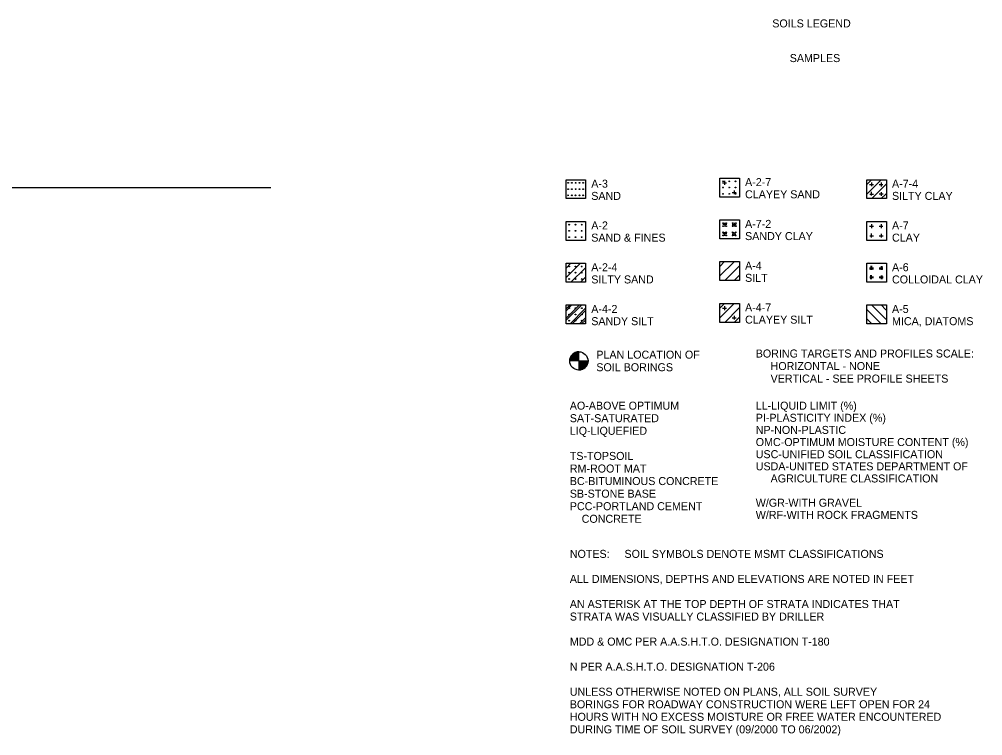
# Model space of a CAD drawing. Extents: x 1.3 to 42.5, y -2.5 to 22.6.
# Drawn here: x 28.02 to 42.47, y 11.81 to 22.56 of the extents above; entities that cross this region are included whole.
import ezdxf

# ---------------------------------------------------------------- set-up
doc = ezdxf.new("R2010")
doc.units = 0
doc.layers.add('B-SOIL-TEXT', color=7, linetype='Continuous')

msp = doc.modelspace()

# ---------------------------------------------------------------- linework, layer by layer
at = {"layer": 'B-SOIL-TEXT'}
for p, q in [((38.568, 20.107), (38.627, 20.107)), ((40.802, 20.154), (40.732, 20.082)), ((40.945, 20.153), (40.732, 19.939)), ((40.945, 20.11), (40.945, 20.053)), ((41.024, 20.089), (41.017, 20.082)), ((20.128, 20.038), (31.791, 20.038)), ((38.713, 19.964), (38.771, 19.964)), ((40.773, 20.082), (40.831, 20.082)), ((40.803, 19.915), (40.803, 19.971)), ((41.016, 20.082), (40.804, 19.87)), ((40.915, 20.082), (40.973, 20.082)), ((41.024, 19.947), (41.017, 19.939)), ((40.775, 19.939), (40.833, 19.939)), ((40.917, 19.94), (40.976, 19.94)), ((41.016, 19.939), (40.947, 19.87)), ((38.631, 19.48), (38.573, 19.48)), ((38.6, 19.508), (38.6, 19.451)), ((38.6, 19.312), (38.6, 19.369)), ((38.71, 19.48), (38.769, 19.48)), ((38.74, 19.312), (38.74, 19.369)), ((38.741, 19.508), (38.741, 19.451)), ((40.773, 19.457), (40.831, 19.457)), ((40.915, 19.456), (40.973, 19.456)), ((40.945, 19.485), (40.945, 19.428)), ((38.631, 19.34), (38.573, 19.34)), ((38.709, 19.34), (38.768, 19.34)), ((40.775, 19.314), (40.833, 19.314)), ((40.803, 19.289), (40.803, 19.346)), ((40.917, 19.314), (40.976, 19.314)), ((36.291, 18.901), (36.22, 18.829)), ((36.434, 18.9), (36.22, 18.687)), ((36.505, 18.829), (36.293, 18.617)), ((36.513, 18.836), (36.505, 18.829)), ((38.598, 18.925), (38.527, 18.853)), ((38.741, 18.924), (38.527, 18.71)), ((38.812, 18.853), (38.6, 18.64)), ((38.82, 18.86), (38.812, 18.853)), ((40.773, 18.83), (40.831, 18.83)), ((40.773, 18.819), (40.831, 18.819)), ((40.915, 18.83), (40.973, 18.83)), ((40.915, 18.819), (40.973, 18.819)), ((40.945, 18.858), (40.945, 18.801)), ((40.957, 18.858), (40.957, 18.801)), ((36.505, 18.687), (36.435, 18.617)), ((36.513, 18.694), (36.505, 18.687)), ((38.812, 18.71), (38.742, 18.64)), ((38.82, 18.717), (38.812, 18.71)), ((40.775, 18.699), (40.833, 18.699)), ((40.775, 18.688), (40.833, 18.688)), ((40.791, 18.663), (40.791, 18.72)), ((40.803, 18.663), (40.803, 18.72)), ((40.917, 18.699), (40.976, 18.699)), ((40.917, 18.688), (40.976, 18.688)), ((36.419, 18.275), (36.22, 18.076)), ((36.274, 18.274), (36.221, 18.219)), ((36.307, 18.275), (36.222, 18.188)), ((36.45, 18.274), (36.222, 18.046)), ((36.507, 18.221), (36.279, 17.992)), ((36.513, 18.224), (36.508, 18.219)), ((38.598, 18.298), (38.527, 18.226)), ((38.741, 18.297), (38.527, 18.084)), ((38.568, 18.226), (38.627, 18.226)), ((38.812, 18.226), (38.6, 18.014)), ((38.82, 18.233), (38.812, 18.226)), ((40.805, 18.274), (41.018, 18.06)), ((40.948, 18.275), (41.018, 18.202)), ((36.506, 18.187), (36.311, 17.992)), ((36.506, 18.077), (36.421, 17.992)), ((36.513, 18.081), (36.508, 18.076)), ((36.513, 18.191), (36.51, 18.188)), ((38.713, 18.084), (38.771, 18.084)), ((38.812, 18.084), (38.742, 18.014)), ((38.82, 18.091), (38.812, 18.084)), ((40.734, 18.202), (40.946, 17.99)), ((41.021, 18.202), (41.024, 18.199)), ((36.505, 18.044), (36.452, 17.991)), ((36.513, 18.049), (36.509, 18.046)), ((40.734, 18.06), (40.804, 17.99)), ((41.021, 18.06), (41.024, 18.057)), ((36.413, 17.436), (36.413, 17.573)), ((36.413, 17.436), (36.276, 17.436)), ((36.413, 17.436), (36.413, 17.436)), ((36.413, 17.436), (36.413, 17.3)), ((36.413, 17.436), (36.549, 17.436))]:
    msp.add_line(p, q, dxfattribs=at)
for points in [[(36.22, 20.154), (36.513, 20.154), (36.513, 19.87), (36.22, 19.87)], [(38.527, 20.178), (38.82, 20.178), (38.82, 19.893), (38.527, 19.893)], [(40.732, 20.154), (41.024, 20.154), (41.024, 19.87), (40.732, 19.87)], [(36.22, 19.528), (36.513, 19.528), (36.513, 19.243), (36.22, 19.243)], [(38.527, 19.551), (38.82, 19.551), (38.82, 19.267), (38.527, 19.267)], [(40.732, 19.528), (41.024, 19.528), (41.024, 19.243), (40.732, 19.243)], [(36.22, 18.901), (36.513, 18.901), (36.513, 18.617), (36.22, 18.617)], [(38.527, 18.925), (38.82, 18.925), (38.82, 18.64), (38.527, 18.64)], [(40.732, 18.901), (41.024, 18.901), (41.024, 18.617), (40.732, 18.617)], [(36.22, 18.275), (36.513, 18.275), (36.513, 17.99), (36.22, 17.99)], [(38.527, 18.298), (38.82, 18.298), (38.82, 18.014), (38.527, 18.014)], [(40.732, 18.275), (41.024, 18.275), (41.024, 17.99), (40.732, 17.99)]]:
    msp.add_lwpolyline(points, close=True, dxfattribs=at)
for points in [[(38.598, 20.136), (38.598, 20.114), (38.598, 20.079)], [(40.802, 20.112), (40.802, 20.089), (40.802, 20.055)], [(38.741, 19.994), (38.741, 19.971), (38.741, 19.937)], [(40.945, 19.969), (40.945, 19.946), (40.945, 19.912)], [(40.802, 19.486), (40.802, 19.463), (40.802, 19.429)], [(40.945, 19.343), (40.945, 19.321), (40.945, 19.287)], [(40.791, 18.86), (40.791, 18.837), (40.791, 18.803)], [(40.802, 18.86), (40.802, 18.837), (40.802, 18.803)], [(40.945, 18.717), (40.945, 18.694), (40.945, 18.66)], [(40.957, 18.717), (40.957, 18.694), (40.957, 18.66)], [(38.598, 18.256), (38.598, 18.233), (38.598, 18.199)], [(38.741, 18.113), (38.741, 18.09), (38.741, 18.056)]]:
    msp.add_lwpolyline(points, dxfattribs=at)
for centre, radius in [((36.25, 20.106), 0.0057), ((36.307, 20.106), 0.0057), ((36.364, 20.106), 0.0057), ((36.421, 20.106), 0.0057), ((36.478, 20.106), 0.0057), ((38.574, 20.13), 0.0057), ((38.668, 20.13), 0.0057), ((38.761, 20.13), 0.0057), ((36.25, 20.013), 0.0057), ((36.307, 20.013), 0.0057), ((36.364, 20.013), 0.0057), ((36.421, 20.013), 0.0057), ((36.478, 20.013), 0.0057), ((38.574, 20.036), 0.0057), ((38.574, 19.943), 0.0057), ((38.668, 20.036), 0.0057), ((38.668, 19.943), 0.0057), ((38.761, 20.036), 0.0057), ((38.761, 19.943), 0.0057), ((36.249, 19.919), 0.0057), ((36.306, 19.919), 0.0057), ((36.363, 19.919), 0.0057), ((36.42, 19.919), 0.0057), ((36.477, 19.919), 0.0057), ((36.267, 19.48), 0.0057), ((36.267, 19.386), 0.0057), ((36.361, 19.48), 0.0057), ((36.361, 19.386), 0.0057), ((36.454, 19.48), 0.0057), ((36.454, 19.386), 0.0057), ((38.576, 19.502), 0.0057), ((38.576, 19.456), 0.0057), ((38.576, 19.364), 0.0057), ((38.622, 19.502), 0.0057), ((38.622, 19.456), 0.0057), ((38.622, 19.364), 0.0057), ((38.718, 19.364), 0.0057), ((38.719, 19.502), 0.0057), ((38.719, 19.456), 0.0057), ((38.764, 19.364), 0.0057), ((38.765, 19.502), 0.0057), ((38.765, 19.456), 0.0057), ((36.267, 19.293), 0.0057), ((36.361, 19.293), 0.0057), ((36.454, 19.293), 0.0057), ((38.576, 19.318), 0.0057), ((38.622, 19.318), 0.0057), ((38.718, 19.318), 0.0057), ((38.764, 19.318), 0.0057), ((36.267, 18.852), 0.0057), ((36.361, 18.852), 0.0057), ((36.454, 18.852), 0.0057), ((36.267, 18.759), 0.0057), ((36.267, 18.665), 0.0057), ((36.361, 18.759), 0.0057), ((36.361, 18.665), 0.0057), ((36.454, 18.759), 0.0057), ((36.454, 18.665), 0.0057), ((36.268, 18.227), 0.0057), ((36.362, 18.227), 0.0057), ((36.455, 18.227), 0.0057), ((36.268, 18.133), 0.0057), ((36.362, 18.133), 0.0057), ((36.455, 18.133), 0.0057), ((36.268, 18.04), 0.0057), ((36.362, 18.04), 0.0057), ((36.455, 18.04), 0.0057), ((36.412, 17.436), 0.137)]:
    msp.add_circle(centre, radius, dxfattribs=at)
for radius, start, end in [(0.137, 90.0009, 180.0009), (0.134, 90.0009, 180.0009), (0.131, 90.0009, 180.0009), (0.128, 90.0009, 180.0009), (0.125, 90.0009, 180.0009), (0.122, 90.0009, 180.0009), (0.12, 90.0009, 180.0009), (0.117, 90.0009, 180.0009), (0.114, 90.0009, 180.0009), (0.111, 90.0009, 180.0009), (0.108, 90.0009, 180.0009), (0.105, 90.0009, 180.0009), (0.103, 90.0009, 180.0009), (0.0997, 90.0009, 180.0009), (0.0968, 90.0009, 180.0009), (0.094, 90.0009, 180.0009), (0.0911, 90.0009, 180.0009), (0.0883, 90.0009, 180.0009), (0.0854, 90.0009, 180.0009), (0.0826, 90.0009, 180.0009), (0.0797, 90.0009, 180.0009), (0.0769, 90.0009, 180.0009), (0.074, 90.0009, 180.0009), (0.0712, 90.0009, 180.0009), (0.0683, 90.0009, 180.0009), (0.0655, 90.0009, 180.0009), (0.0626, 90.0009, 180.0009), (0.0598, 90.0009, 180.0009), (0.057, 90.0009, 180.0009), (0.0541, 90.0009, 180.0009), (0.0513, 90.0009, 180.0009), (0.0484, 90.0009, 180.0009), (0.0456, 90.0009, 180.0009), (0.0427, 90.0009, 180.0009), (0.0399, 90.0009, 180.0009), (0.037, 90.0009, 180.0009), (0.0342, 90.0009, 180.0009), (0.0313, 90.0009, 180.0009), (0.0285, 90.0009, 180.0009), (0.0256, 90.0009, 180.0009), (0.0228, 90.0009, 180.0009), (0.0199, 90.0009, 180.0009), (0.0171, 90.0009, 180.0009), (0.0142, 90.0009, 180.0009), (0.0114, 90.0009, 180.0009), (0.00854, 90.0009, 180.0009), (0.0057, 90.0009, 180.0009), (0.00285, 90.0009, 180.0009), (0.137, 270.0009, 0.0009), (0.134, 270.0009, 0.0009), (0.131, 270.0009, 0.0009), (0.128, 270.0009, 0.0009), (0.125, 270.0009, 0.0009), (0.122, 270.0009, 0.0009), (0.12, 270.0009, 0.0009), (0.117, 270.0009, 0.0009), (0.114, 270.0009, 0.0009), (0.111, 270.0009, 0.0009), (0.108, 270.0009, 0.0009), (0.105, 270.0009, 0.0009), (0.103, 270.0009, 0.0009), (0.0997, 270.0009, 0.0009), (0.0968, 270.0009, 0.0009), (0.094, 270.0009, 0.0009), (0.0911, 270.0009, 0.0009), (0.0883, 270.0009, 0.0009), (0.0854, 270.0009, 0.0009), (0.0826, 270.0009, 0.0009), (0.0797, 270.0009, 0.0009), (0.0769, 270.0009, 0.0009), (0.074, 270.0009, 0.0009), (0.0712, 270.0009, 0.0009), (0.0683, 270.0009, 0.0009), (0.0655, 270.0009, 0.0009), (0.0626, 270.0009, 0.0009), (0.0598, 270.0009, 0.0009), (0.057, 270.0009, 0.0009), (0.0541, 270.0009, 0.0009), (0.0513, 270.0009, 0.0009), (0.0484, 270.0009, 0.0009), (0.0456, 270.0009, 0.0009), (0.0427, 270.0009, 0.0009), (0.0399, 270.0009, 0.0009), (0.037, 270.0009, 0.0009), (0.0342, 270.0009, 0.0009), (0.0313, 270.0009, 0.0009), (0.0285, 270.0009, 0.0009), (0.0256, 270.0009, 0.0009), (0.0228, 270.0009, 0.0009), (0.0199, 270.0009, 0.0009), (0.0171, 270.0009, 0.0009), (0.0142, 270.0009, 0.0009), (0.0114, 270.0009, 0.0009), (0.00854, 270.0009, 0.0009), (0.0057, 270.0009, 0.0009), (0.00285, 270.0009, 0.0009)]:
    msp.add_arc((36.412, 17.436), radius, start, end, dxfattribs=at)

# ---------------------------------------------------------------- texts
for s, p in [('SOILS LEGEND', (39.313, 22.438)), ('SAMPLES', (39.575, 21.918)), ('A-3', (36.598, 20.034)), ('A-2-7', (38.905, 20.058)), ('A-7-4', (41.109, 20.034)), ('SAND', (36.598, 19.851)), ('CLAYEY SAND', (38.905, 19.875)), ('SILTY CLAY', (41.109, 19.851)), ('A-2', (36.598, 19.408)), ('A-7-2', (38.905, 19.431)), ('A-7', (41.109, 19.408)), ('SANDY CLAY', (38.905, 19.248)), ('SAND & FINES', (36.598, 19.225)), ('CLAY', (41.109, 19.225)), ('A-2-4', (36.598, 18.781)), ('A-4', (38.905, 18.805)), ('A-6', (41.109, 18.781)), ('SILTY SAND', (36.598, 18.598)), ('SILT', (38.905, 18.622)), ('COLLOIDAL CLAY', (41.109, 18.598)), ('A-4-2', (36.598, 18.155)), ('A-4-7', (38.905, 18.178)), ('A-5', (41.109, 18.155)), ('SANDY SILT', (36.598, 17.972)), ('CLAYEY SILT', (38.905, 17.995)), ('MICA, DIATOMS', (41.109, 17.972)), ('PLAN LOCATION OF ', (36.674, 17.47)), ('BORING TARGETS AND PROFILES SCALE:', (39.065, 17.487)), ('SOIL BORINGS', (36.674, 17.281)), ('     HORIZONTAL - NONE', (39.065, 17.299)), ('     VERTICAL - SEE PROFILE SHEETS', (39.065, 17.111)), ('AO-ABOVE OPTIMUM', (36.276, 16.705)), ('LL-LIQUID LIMIT (%)', (39.065, 16.705)), ('SAT-SATURATED', (36.276, 16.517)), ('PI-PLASTICITY INDEX (%)', (39.065, 16.523)), ('LIQ-LIQUEFIED', (36.276, 16.328)), ('NP-NON-PLASTIC', (39.065, 16.341)), ('OMC-OPTIMUM MOISTURE CONTENT (%)', (39.065, 16.159)), ('TS-TOPSOIL', (36.276, 15.951)), ('USC-UNIFIED SOIL CLASSIFICATION', (39.065, 15.977)), ('USDA-UNITED STATES DEPARTMENT OF', (39.065, 15.795)), ('RM-ROOT MAT', (36.276, 15.762)), ('BC-BITUMINOUS CONCRETE', (36.276, 15.574)), ('     AGRICULTURE CLASSIFICATION', (39.065, 15.613)), ('SB-STONE BASE', (36.276, 15.385)), ('PCC-PORTLAND CEMENT', (36.276, 15.197)), ('W/GR-WITH GRAVEL', (39.065, 15.249)), ('W/RF-WITH ROCK FRAGMENTS', (39.065, 15.067)), ('    CONCRETE', (36.276, 15.008)), ('NOTES:     SOIL SYMBOLS DENOTE MSMT CLASSIFICATIONS', (36.276, 14.482)), ('ALL DIMENSIONS, DEPTHS AND ELEVATIONS ARE NOTED IN FEET', (36.276, 14.106)), ('AN ASTERISK AT THE TOP DEPTH OF STRATA INDICATES THAT ', (36.276, 13.73)), ('STRATA WAS VISUALLY CLASSIFIED BY DRILLER', (36.276, 13.542)), ('MDD & OMC PER A.A.S.H.T.O. DESIGNATION T-180', (36.276, 13.166)), ('N PER A.A.S.H.T.O. DESIGNATION T-206', (36.276, 12.79)), ('UNLESS OTHERWISE NOTED ON PLANS, ALL SOIL SURVEY ', (36.276, 12.414)), ('BORINGS FOR ROADWAY CONSTRUCTION WERE LEFT OPEN FOR 24 ', (36.276, 12.226)), ('HOURS WITH NO EXCESS MOISTURE OR FREE WATER ENCOUNTERED ', (36.276, 12.038)), ('DURING TIME OF SOIL SURVEY (09/2000 TO 06/2002)', (36.276, 11.85))]:
    msp.add_text(s, height=0.12, dxfattribs=at).set_placement(p)

doc.saveas('drawing.dxf')
